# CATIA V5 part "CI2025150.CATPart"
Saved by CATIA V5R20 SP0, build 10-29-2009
Part number: CI2025150
Bounding box of the stored display mesh (mm): x -24 to 24, y -18.97 to 184.5, z -32.903 to 26.909
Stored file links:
  C:\Users\Raffaele\Desktop\3D X SITO CF\BOLEX\19-INCLINED ASSEMBLY REF_CI\CI2025150.CATPart

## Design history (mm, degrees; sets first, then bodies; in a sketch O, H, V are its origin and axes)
Set1
  DatumSurface1 to DatumSurface16 "MANIFOLD_SOLID_BREP #393"
  DatumSurface17 to DatumSurface39 "MANIFOLD_SOLID_BREP #1138"
Body1 (main body)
